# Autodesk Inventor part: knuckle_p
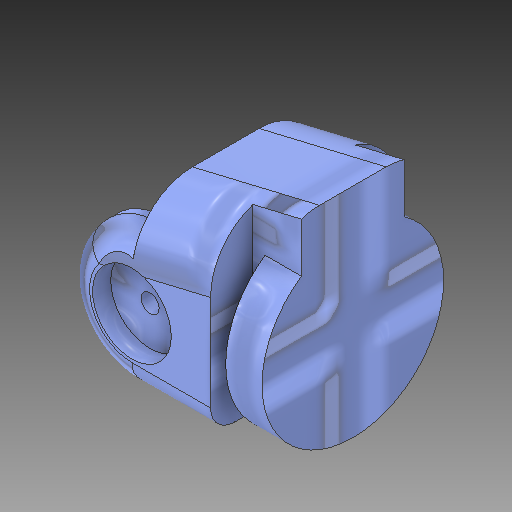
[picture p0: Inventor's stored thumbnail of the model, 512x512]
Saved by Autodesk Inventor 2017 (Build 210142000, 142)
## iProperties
Created: 2017-05
Part Number: knuckle_p
Material: Generic
Document SubType Name: Modeling
Designer: alez_
Density: 1 g/cm^3
Appearance: Default
Author: alez_
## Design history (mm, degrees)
derived "knuckle.ipt" dims "d0" = 9
feature "Solid1::knuckle.ipt" dims "d0" = 9
tag "TaggingFeature1"
body "Solid1"
